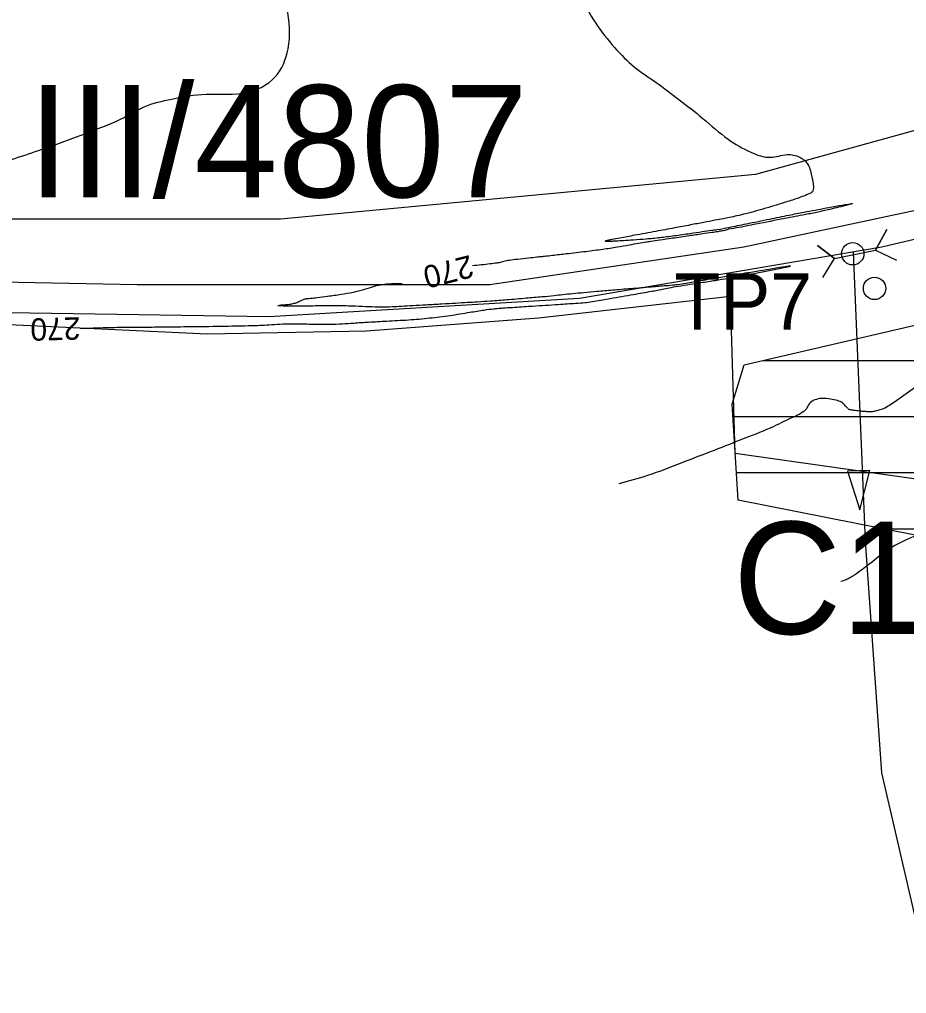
# Model space of a CAD drawing. Extents: x -478232 to -472707, y -1118753 to -1113967.
# Drawn here: x -477225.9 to -477067.7, y -1117543.2 to -1117369.5 of the extents above; entities that cross this region are included whole.
import ezdxf

# ---------------------------------------------------------------- set-up
doc = ezdxf.new("R2010")
doc.units = 0
for name, color, linetype in [('cesty', 7, 'Continuous'), ('DESQ_pomoc', 7, 'Continuous'), ('meliorace', 7, 'Continuous'), ('ObPÚ', 7, 'Continuous'), ('silnice', 7, 'Continuous'), ('TP _navrh', 7, 'Continuous'), ('Vrstevnice_hlavni', 7, 'Continuous'), ('Vrstevnice_popis', 7, 'Continuous'), ('Vrstevnice_vedlejsi', 7, 'Continuous')]:
    doc.layers.add(name, color=color, linetype=linetype)

msp = doc.modelspace()

# ---------------------------------------------------------------- linework, layer by layer
at = {"layer": 'cesty'}
msp.add_line((-477074.24, -1117449.956), (-477078.239, -1117450.07), dxfattribs=at)
msp.add_lwpolyline([(-477078.239, -1117450.07), (-477076.041, -1117456.957), (-477074.24, -1117449.956)], dxfattribs=at)
for centre in [(-477077.306, -1117411.294), (-477073.414, -1117417.47)]:
    msp.add_circle(centre, 2, dxfattribs=at)
at = {"layer": 'DESQ_pomoc'}
for points in [[(-477004.483, -1117160.333), (-477044.314, -1117201.613), (-476989.999, -1117272.585), (-476948.719, -1117345.73), (-476963.565, -1117360.938), (-477094.646, -1117397.148), (-477179.378, -1117405.115), (-477285.113, -1117405.115), (-477363.689, -1117381.578), (-477420.306, -1117340.062)], [(-477020.868, -1117742.21), (-477020.868, -1117712.88), (-477044.921, -1117619.616), (-477020.387, -1117525.382), (-477007.841, -1117474.78), (-476980.24, -1117427.384), (-476963.584, -1117391.711), (-476964.987, -1117380.26), (-476992.688, -1117391.394), (-477072.131, -1117410.121), (-477126.017, -1117419.251), (-477181.42, -1117422.538), (-477293.867, -1117420.815), (-477420.422, -1117416.561)], [(-477077.244, -1117410.976), (-477075.072, -1117462.576), (-477072.175, -1117503.856), (-477064.437, -1117537.231), (-477057.691, -1117586.596), (-477044.921, -1117619.616)]]:
    msp.add_lwpolyline(points, dxfattribs=at)
at = {"layer": 'meliorace'}
for p, q in [((-477093.346, -1117430.324), (-476251.695, -1117430.324)), ((-477098.695, -1117440.324), (-476258.997, -1117440.324)), ((-477098.068, -1117450.324), (-476269.242, -1117450.324)), ((-477072.131, -1117460.324), (-476277.203, -1117460.324))]:
    msp.add_line(p, q, dxfattribs=at)
for points in [[(-477096.685, -1117431.098), (-476996.826, -1117407.945), (-476867.976, -1117358.62), (-476701.545, -1117295.201), (-476565.179, -1117253.929), (-476541.556, -1117247.889), (-476396.6, -1117242.856), (-476308.552, -1117238.83)], [(-476280.85, -1117490.49), (-476374.051, -1117463.31), (-476374.051, -1117487.47), (-476380.494, -1117525.722), (-476380.494, -1117534.782), (-476500.754, -1117537.802), (-476551.22, -1117535.789), (-476674.701, -1117521.696), (-476844.354, -1117500.556), (-476939.917, -1117486.463), (-477097.759, -1117455.257), (-477098.832, -1117438.144), (-477096.685, -1117431.098)]]:
    msp.add_lwpolyline(points, dxfattribs=at)
at = {"layer": 'ObPÚ'}
msp.add_lwpolyline([(-476315.84, -1117537.76), (-476383.34, -1117541.03), (-476418.4, -1117542.71), (-476545.68, -1117541.31), (-476626.45, -1117531.73), (-476742.52, -1117514.65), (-476868.42, -1117495.62), (-476991.41, -1117464.75), (-477034.12, -1117456), (-477098.26, -1117446.89), (-477099.13, -1117418.94), (-477133.34, -1117422.81), (-477164.02, -1117425.11), (-477192.43, -1117425.62), (-477239.17, -1117423.45), (-477286.2, -1117422.09), (-477330.75, -1117420.42), (-477373.93, -1117418.61), (-477420.9, -1117417.49), (-477422.1, -1117417.56), (-477424.2, -1117417.6), (-477428.82, -1117417.33), (-477494.83, -1117414.18)], dxfattribs=at)
at = {"layer": 'silnice'}
msp.add_lwpolyline([(-478068.596, -1117511.329), (-477917.95, -1117462.993), (-477779.219, -1117418.245), (-477732.944, -1117407.585), (-477720.808, -1117405.048), (-477704.588, -1117403.835), (-477689.402, -1117401.926), (-477652.852, -1117401.691), (-477590.784, -1117403.37), (-477332.447, -1117414.279), (-477204.956, -1117416.797), (-477142.049, -1117416.797), (-477096.756, -1117410.083), (-477036.34, -1117397.174), (-476978.492, -1117379.033), (-476883.712, -1117344.626), (-476756.221, -1117298.47), (-476633.763, -1117254.832), (-476588.47, -1117242.245), (-476550.726, -1117234.692), (-476503.755, -1117230.496), (-476424.073, -1117228.817), (-476282.324, -1117220.425)], dxfattribs=at)
at = {"layer": 'TP _navrh'}
msp.add_lwpolyline([(-477082.648, -1117415.535), (-477080.577, -1117412.153), (-477083.585, -1117409.799), (-477080.577, -1117412.153), (-477073.221, -1117410.681), (-477071.201, -1117406.996), (-477073.221, -1117410.681), (-477069.519, -1117412.454)], dxfattribs=at)
at = {"layer": 'Vrstevnice_hlavni'}
for points in [[(-477146.824, -1117341.669), (-477145.53, -1117343.787), (-477143.377, -1117346.176), (-477139.718, -1117349.895), (-477134.552, -1117354.944), (-477130.069, -1117360.01), (-477126.268, -1117365.094), (-477123.149, -1117370.196), (-477119.793, -1117374.506), (-477116.199, -1117378.023), (-477112.366, -1117380.748), (-477108.306, -1117383.799), (-477104.018, -1117387.175), (-477099.503, -1117390.877), (-477095.493, -1117393.186), (-477091.99, -1117394.101), (-477088.994, -1117393.622), (-477086.761, -1117394.056), (-477085.292, -1117395.404), (-477084.588, -1117397.664), (-477084.327, -1117399.29), (-477084.51, -1117400.281), (-477085.136, -1117400.637), (-477086.322, -1117401.118), (-477088.065, -1117401.724), (-477090.368, -1117402.454), (-477092.519, -1117403.102), (-477094.519, -1117403.67), (-477096.367, -1117404.156), (-477097.959, -1117404.548), (-477099.295, -1117404.845), (-477100.373, -1117405.048), (-477101.892, -1117405.335), (-477103.852, -1117405.707), (-477106.253, -1117406.164), (-477109.112, -1117406.7), (-477112.43, -1117407.317), (-477116.206, -1117408.013), (-477118.824, -1117408.497), (-477120.282, -1117408.769), (-477120.582, -1117408.829), (-477120.856, -1117408.889), (-477121.104, -1117408.949), (-477121.327, -1117409.008), (-477121.439, -1117409.049), (-477121.438, -1117409.073), (-477121.325, -1117409.08), (-477120.969, -1117409.07), (-477120.369, -1117409.044), (-477119.525, -1117409.002), (-477118.208, -1117408.919), (-477116.418, -1117408.796), (-477114.154, -1117408.634), (-477111.719, -1117408.391), (-477109.113, -1117408.069), (-477106.335, -1117407.667), (-477104.138, -1117407.351), (-477102.519, -1117407.12), (-477101.48, -1117406.975), (-477099.399, -1117406.591), (-477096.275, -1117405.967), (-477092.108, -1117405.104), (-477088.677, -1117404.405), (-477085.981, -1117403.872), (-477084.021, -1117403.503), (-477082.051, -1117403.14), (-477080.072, -1117402.783), (-477078.082, -1117402.431), (-477077.377, -1117402.351), (-477077.958, -1117402.544), (-477079.824, -1117403.01), (-477081.362, -1117403.385), (-477082.573, -1117403.669), (-477083.456, -1117403.863), (-477085.748, -1117404.319), (-477089.45, -1117405.037), (-477094.562, -1117406.017), (-477098.043, -1117406.693), (-477099.892, -1117407.066), (-477100.11, -1117407.135), (-477100.605, -1117407.234), (-477101.377, -1117407.364), (-477102.428, -1117407.524), (-477104.122, -1117407.774), (-477106.461, -1117408.115), (-477109.445, -1117408.547), (-477111.728, -1117408.88), (-477113.312, -1117409.116), (-477114.195, -1117409.253), (-477115.488, -1117409.47), (-477117.191, -1117409.767), (-477119.302, -1117410.144), (-477121.873, -1117410.531), (-477124.905, -1117410.928), (-477128.396, -1117411.335), (-477130.859, -1117411.619), (-477132.294, -1117411.781)], [(-477215.088, -1117424.598), (-477213.883, -1117424.565), (-477213.045, -1117424.54), (-477211.973, -1117424.505), (-477210.665, -1117424.461), (-477208.993, -1117424.426), (-477206.957, -1117424.4), (-477204.557, -1117424.383), (-477200.902, -1117424.346), (-477195.994, -1117424.287), (-477189.831, -1117424.207), (-477185.108, -1117424.11), (-477181.825, -1117423.993), (-477179.982, -1117423.859), (-477177.885, -1117423.792), (-477175.534, -1117423.793), (-477172.928, -1117423.862), (-477170.52, -1117423.861), (-477168.309, -1117423.789), (-477166.295, -1117423.647), (-477163.661, -1117423.482), (-477160.406, -1117423.294), (-477156.531, -1117423.082), (-477152.771, -1117422.751), (-477149.127, -1117422.301), (-477145.598, -1117421.731), (-477143.017, -1117421.333), (-477141.382, -1117421.107), (-477140.694, -1117421.052), (-477140.121, -1117421.007), (-477139.663, -1117420.971), (-477139.321, -1117420.944), (-477137.566, -1117420.828), (-477134.397, -1117420.622), (-477129.815, -1117420.327), (-477126.699, -1117420.123), (-477125.051, -1117420.012), (-477124.871, -1117419.993), (-477123.368, -1117419.743), (-477120.545, -1117419.262), (-477116.4, -1117418.55), (-477113.211, -1117417.987), (-477110.978, -1117417.574), (-477109.7, -1117417.309), (-477107.955, -1117416.998), (-477105.743, -1117416.642), (-477103.065, -1117416.239), (-477100.638, -1117415.85), (-477098.462, -1117415.474), (-477096.537, -1117415.112), (-477094.355, -1117414.691), (-477091.917, -1117414.211), (-477089.223, -1117413.674), (-477088.382, -1117413.476), (-477089.394, -1117413.618), (-477092.259, -1117414.101), (-477094.404, -1117414.457), (-477095.829, -1117414.686), (-477096.534, -1117414.788), (-477098.207, -1117415.065), (-477100.848, -1117415.518), (-477104.456, -1117416.145), (-477107.024, -1117416.582), (-477108.55, -1117416.828), (-477109.036, -1117416.884), (-477110.59, -1117417.022), (-477113.213, -1117417.241), (-477116.904, -1117417.542), (-477120.138, -1117417.812), (-477122.916, -1117418.049), (-477125.238, -1117418.254), (-477127.285, -1117418.447), (-477129.059, -1117418.627), (-477130.56, -1117418.795), (-477132.715, -1117419.001), (-477135.525, -1117419.247), (-477138.99, -1117419.531), (-477141.893, -1117419.754), (-477144.236, -1117419.917), (-477146.017, -1117420.019), (-477148.13, -1117420.141), (-477150.574, -1117420.283), (-477153.35, -1117420.444), (-477155.754, -1117420.581), (-477157.784, -1117420.693), (-477159.442, -1117420.78), (-477161.361, -1117420.806), (-477163.542, -1117420.768), (-477165.985, -1117420.669), (-477167.626, -1117420.602), (-477168.467, -1117420.568), (-477168.506, -1117420.567), (-477169.564, -1117420.577), (-477171.641, -1117420.598), (-477174.737, -1117420.631), (-477176.863, -1117420.651), (-477178.019, -1117420.66)], [(-477132.294, -1117411.781), (-477132.702, -1117411.819), (-477133.641, -1117411.918), (-477135.111, -1117412.077), (-477137.112, -1117412.297), (-477138.59, -1117412.492), (-477139.543, -1117412.664), (-477139.973, -1117412.813), (-477140.784, -1117412.965), (-477141.975, -1117413.121), (-477145.12, -1117413.439)], [(-477178.019, -1117420.66), (-477178.206, -1117420.656), (-477178.505, -1117420.644), (-477178.915, -1117420.624), (-477179.436, -1117420.594), (-477179.751, -1117420.564), (-477179.859, -1117420.533), (-477179.759, -1117420.502), (-477179.373, -1117420.452), (-477178.702, -1117420.382), (-477177.744, -1117420.294), (-477176.924, -1117420.136), (-477176.242, -1117419.908), (-477175.698, -1117419.612), (-477175.145, -1117419.4), (-477174.582, -1117419.274), (-477174.009, -1117419.233), (-477172.81, -1117419.094), (-477170.984, -1117418.858), (-477168.53, -1117418.525), (-477166.373, -1117418.134), (-477164.512, -1117417.686), (-477162.947, -1117417.181), (-477161.494, -1117416.836), (-477160.151, -1117416.651), (-477157.689, -1117416.6)]]:
    msp.add_spline(points, degree=3, dxfattribs=at)
at = {"layer": 'Vrstevnice_vedlejsi'}
for points in [[(-477242.816, -1117401.206), (-477242.33, -1117400.788), (-477241.801, -1117400.341), (-477241.229, -1117399.866), (-477240.615, -1117399.363), (-477236.987, -1117397.929), (-477230.346, -1117395.561), (-477220.692, -1117392.262), (-477213.029, -1117389.419), (-477207.358, -1117387.033), (-477203.679, -1117385.104), (-477198.765, -1117383.705), (-477192.616, -1117382.835), (-477185.231, -1117382.494), (-477180.359, -1117379.804), (-477178.001, -1117374.763), (-477178.155, -1117367.373), (-477179.951, -1117358.721), (-477183.387, -1117348.807), (-477188.465, -1117337.631), (-477192.245, -1117329.464), (-477194.727, -1117324.304), (-477195.91, -1117322.151), (-477197.022, -1117320.01), (-477198.062, -1117317.881), (-477199.031, -1117315.762), (-477201.828, -1117310.612), (-477206.453, -1117302.429), (-477212.906, -1117291.215), (-477218.991, -1117279.805), (-477224.706, -1117268.2), (-477230.053, -1117256.4), (-477233.791, -1117248.023), (-477235.922, -1117243.067), (-477236.445, -1117241.534), (-477237.131, -1117240.196), (-477237.979, -1117239.054), (-477238.989, -1117238.108), (-477240.099, -1117237.792), (-477241.308, -1117238.108), (-477242.616, -1117239.054), (-477247.496, -1117242.927), (-477255.949, -1117249.728), (-477267.975, -1117259.456), (-477276.908, -1117266.227), (-477282.75, -1117270.039), (-477285.501, -1117270.894), (-477290.862, -1117272.253), (-477298.834, -1117274.115), (-477309.417, -1117276.481), (-477320.28, -1117277.55), (-477331.422, -1117277.32), (-477342.843, -1117275.793), (-477351.095, -1117274.483), (-477356.177, -1117273.39), (-477358.088, -1117272.515), (-477363.807, -1117268.569), (-477373.333, -1117261.552), (-477386.667, -1117251.464), (-477395.708, -1117244.586), (-477400.459, -1117240.917), (-477400.917, -1117240.459), (-477405.515, -1117237.519), (-477414.252, -1117232.098), (-477427.127, -1117224.195), (-477436.796, -1117218.202), (-477443.259, -1117214.119), (-477446.516, -1117211.946), (-477449.727, -1117209.411), (-477452.893, -1117206.515), (-477456.014, -1117203.258), (-477459.048, -1117199.241), (-477461.994, -1117194.464), (-477464.853, -1117188.928), (-477466.734, -1117184.683), (-477467.638, -1117181.729), (-477467.564, -1117180.066), (-477467.628, -1117178.904), (-477467.829, -1117178.243), (-477468.169, -1117178.084), (-477468.447, -1117177.976), (-477468.662, -1117177.92), (-477468.815, -1117177.914), (-477468.774, -1117177.844), (-477468.538, -1117177.708), (-477468.108, -1117177.506), (-477467.675, -1117177.3), (-477467.24, -1117177.089), (-477466.803, -1117176.874), (-477466.105, -1117176.551), (-477465.147, -1117176.119), (-477463.929, -1117175.579), (-477461.972, -1117174.773), (-477459.277, -1117173.703), (-477455.843, -1117172.368), (-477453.286, -1117171.289), (-477451.604, -1117170.465)], [(-476949.399, -1117372.225), (-476950.054, -1117372.441), (-476951.675, -1117373.023), (-476954.263, -1117373.972), (-476957.816, -1117375.288), (-476960.377, -1117376.228), (-476961.947, -1117376.791), (-476962.524, -1117376.977), (-476963.443, -1117377.294), (-476964.702, -1117377.74), (-476966.303, -1117378.316), (-476967.847, -1117378.881), (-476969.334, -1117379.436), (-476970.765, -1117379.98), (-476971.749, -1117380.352), (-476972.286, -1117380.554), (-476972.376, -1117380.584), (-476972.46, -1117380.603), (-476972.535, -1117380.61), (-476972.604, -1117380.606), (-476972.738, -1117380.627), (-476972.936, -1117380.673), (-476973.2, -1117380.744), (-476974.259, -1117381.096), (-476976.114, -1117381.728), (-476978.764, -1117382.642), (-476980.7, -1117383.319), (-476981.922, -1117383.76), (-476982.43, -1117383.965), (-476982.785, -1117384.141), (-476982.985, -1117384.289), (-476983.032, -1117384.407), (-476983.153, -1117384.527), (-476983.35, -1117384.648), (-476983.621, -1117384.77), (-476984.527, -1117385.236), (-476986.068, -1117386.046), (-476988.244, -1117387.2), (-476990.079, -1117388.126), (-476991.573, -1117388.823), (-476992.727, -1117389.293), (-476993.599, -1117389.623), (-476994.191, -1117389.814), (-476994.501, -1117389.866), (-476994.773, -1117389.859), (-476995.007, -1117389.794), (-476995.204, -1117389.67), (-476995.432, -1117389.572), (-476995.691, -1117389.498), (-476995.982, -1117389.45), (-476996.366, -1117389.475), (-476996.841, -1117389.574), (-476997.408, -1117389.746), (-476998.778, -1117390.211), (-477000.95, -1117390.967), (-477003.925, -1117392.016), (-477005.929, -1117392.723), (-477006.96, -1117393.089), (-477007.02, -1117393.114), (-477007.125, -1117393.156), (-477007.275, -1117393.216), (-477007.47, -1117393.295), (-477008.52, -1117393.762), (-477010.425, -1117394.619), (-477013.185, -1117395.865), (-477015.943, -1117397.083), (-477018.699, -1117398.275), (-477021.454, -1117399.44), (-477024.911, -1117400.943), (-477029.072, -1117402.785), (-477033.934, -1117404.965), (-477037.348, -1117406.72), (-477039.312, -1117408.05), (-477039.827, -1117408.956), (-477040.522, -1117410.656), (-477041.396, -1117413.151), (-477042.45, -1117416.441), (-477043.162, -1117418.65), (-477043.53, -1117419.779), (-477043.555, -1117419.828), (-477043.655, -1117419.904), (-477043.83, -1117420.007), (-477044.079, -1117420.138), (-477044.728, -1117420.371), (-477045.775, -1117420.705), (-477047.22, -1117421.141), (-477048.311, -1117421.564), (-477049.047, -1117421.973), (-477049.428, -1117422.368), (-477050.488, -1117423.229), (-477052.226, -1117424.555), (-477054.643, -1117426.346), (-477057.763, -1117428.695), (-477061.585, -1117431.601), (-477066.11, -1117435.065), (-477069.43, -1117437.475), (-477071.544, -1117438.831)], [(-476974.733, -1117386.682), (-476975.277, -1117387.275), (-476975.702, -1117387.827), (-476976.007, -1117388.339), (-476976.193, -1117388.809), (-476977.422, -1117389.621), (-476979.694, -1117390.774), (-476983.01, -1117392.269), (-476985.24, -1117393.275), (-476986.384, -1117393.794), (-476986.443, -1117393.825), (-476986.492, -1117393.85), (-476986.532, -1117393.868), (-476986.563, -1117393.881), (-476987.653, -1117394.068), (-476989.803, -1117394.429), (-476993.013, -1117394.966), (-476995.178, -1117395.307), (-476996.298, -1117395.454), (-476996.374, -1117395.407), (-476996.618, -1117395.448), (-476997.03, -1117395.577), (-476997.611, -1117395.795), (-476998.462, -1117396.152), (-476999.583, -1117396.646), (-477000.973, -1117397.278), (-477001.843, -1117397.944), (-477002.191, -1117398.645), (-477002.019, -1117399.38), (-477002.861, -1117401.234), (-477004.718, -1117404.207), (-477007.59, -1117408.299), (-477010.065, -1117412.279), (-477012.143, -1117416.145), (-477013.825, -1117419.897), (-477015.18, -1117422.513), (-477016.209, -1117423.993), (-477016.911, -1117424.335), (-477017.819, -1117424.794), (-477018.933, -1117425.37), (-477020.251, -1117426.063), (-477021.596, -1117427.102), (-477022.968, -1117428.486), (-477024.366, -1117430.216), (-477026.475, -1117432.724), (-477029.296, -1117436.011), (-477032.827, -1117440.076), (-477035.789, -1117443.588), (-477038.18, -1117446.547), (-477040.002, -1117448.952), (-477041.26, -1117450.593), (-477041.954, -1117451.468), (-477042.085, -1117451.578), (-477043.235, -1117452.282), (-477045.403, -1117453.579), (-477048.59, -1117455.47), (-477052.543, -1117457.235), (-477057.261, -1117458.873), (-477062.744, -1117460.385), (-477067.379, -1117462.154), (-477071.166, -1117464.181), (-477074.104, -1117466.466), (-477076.302, -1117468.1), (-477077.758, -1117469.084), (-477078.473, -1117469.418), (-477079.423, -1117469.758)], [(-477071.544, -1117438.831), (-477072.451, -1117439.133), (-477073.216, -1117439.342), (-477073.837, -1117439.459), (-477074.315, -1117439.483), (-477074.977, -1117439.456), (-477075.825, -1117439.378), (-477076.857, -1117439.25), (-477077.561, -1117439.154), (-477077.938, -1117439.091), (-477077.986, -1117439.061), (-477078.2, -1117438.853), (-477078.58, -1117438.467), (-477079.126, -1117437.904), (-477080.016, -1117437.489), (-477081.252, -1117437.224), (-477082.833, -1117437.106), (-477084.091, -1117437.363), (-477085.025, -1117437.993), (-477085.635, -1117438.996), (-477087.761, -1117440.366), (-477091.403, -1117442.102), (-477096.561, -1117444.205), (-477102.031, -1117446.365), (-477107.813, -1117448.585), (-477113.906, -1117450.862), (-477119.042, -1117452.341)]]:
    msp.add_spline(points, degree=3, dxfattribs=at)

# ---------------------------------------------------------------- texts
at = {"layer": 'cesty'}
msp.add_text('C14', height=20, rotation=359.99999, dxfattribs=at).set_placement((-477098.651, -1117479.099))
at = {"layer": 'silnice'}
msp.add_text('III/4807', height=20, dxfattribs=at).set_placement((-477224.453, -1117401.229))
at = {"layer": 'TP _navrh'}
msp.add_text('TP7', height=10, rotation=359.99999, dxfattribs=at).set_placement((-477109.098, -1117424.812))
at = {"layer": 'Vrstevnice_popis'}
for rotation, p in [(194.17065, (-477144.135, -1117411.123)), (181.52987, (-477213.619, -1117422.557))]:
    msp.add_text(' 270 ', height=4, rotation=rotation, dxfattribs=at).set_placement(p)

doc.saveas('drawing.dxf')
